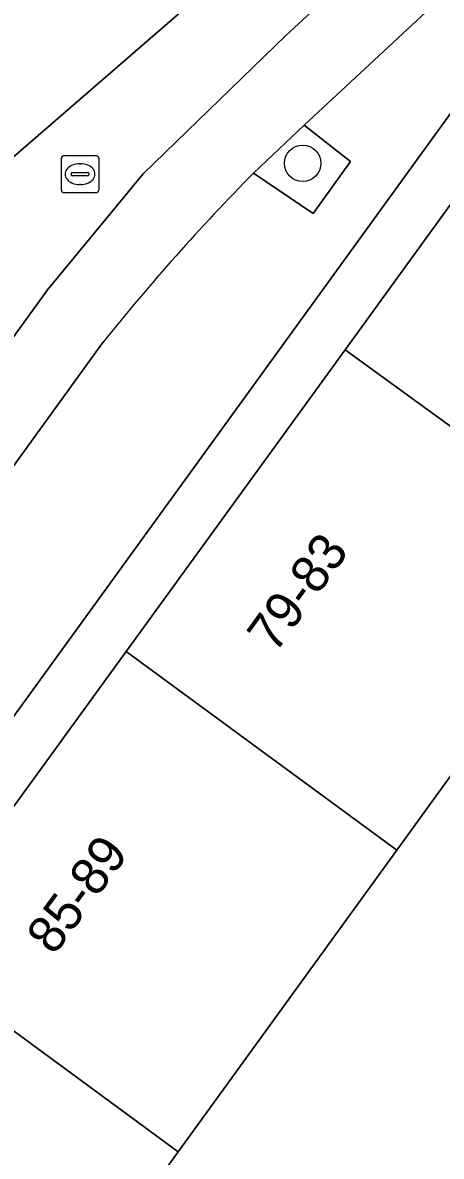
# Model space of a CAD drawing. Extents: x 160102 to 160934, y 382045 to 382923.
# Drawn here: x 160615.06 to 160626.3, y 382711.53 to 382741.96 of the extents above; entities that cross this region are included whole.
import ezdxf

# ---------------------------------------------------------------- set-up
doc = ezdxf.new("R2010")
doc.units = 0
for name, color, linetype in [('IMGEO_Berm_groen', 7, 'Continuous'), ('IMGEO_Boom', 7, 'Continuous'), ('IMGEO_Erf', 7, 'Continuous'), ('IMGEO_Fietspad_gesloten', 7, 'Continuous'), ('IMGEO_Groenvoorziening', 7, 'Continuous'), ('IMGEO_Pand', 7, 'Continuous'), ('IMGEO_Pand_nummerreeks', 7, 'Continuous'), ('IMGEO_Rijbaan_lokaal_gesloten', 7, 'Continuous'), ('IMGEO_Rioolput', 7, 'Continuous'), ('IMGEO_Voetpad_open', 7, 'Continuous')]:
    doc.layers.add(name, color=color, linetype=linetype)

msp = doc.modelspace()

# ---------------------------------------------------------------- linework, layer by layer
at = {"layer": 'IMGEO_Berm_groen'}
for points in [[(160622.116, 382741.606), (160628.941, 382747.912), (160627.337, 382749.441), (160623.499, 382745.883), (160607.777, 382732.272), (160608.096, 382731.058)], [(160611, 382728.257), (160615.726, 382734.786), (160618.296, 382737.897), (160622.116, 382741.606)]]:
    msp.add_lwpolyline(points, dxfattribs=at)
at = {"layer": 'IMGEO_Boom'}
msp.add_circle((160622.58, 382738.184), 0.489, dxfattribs=at)
at = {"layer": 'IMGEO_Erf'}
for points in [[(160627.863, 382741.339), (160608.036, 382713.994), (160608.819, 382712.639), (160609.972, 382710.65), (160610.852, 382711.865), (160612.557, 382710.607), (160614.002, 382712.583), (160610.577, 382715.045), (160610.561, 382715.057), (160611.962, 382716.987), (160617.837, 382725.08), (160623.717, 382733.179), (160629.709, 382741.434)], [(160631.007, 382727.887), (160625.108, 382719.746), (160619.24, 382711.648), (160617.366, 382709.062)]]:
    msp.add_lwpolyline(points, dxfattribs=at)
at = {"layer": 'IMGEO_Fietspad_gesloten'}
for points in [[(160680.167, 382795.521), (160667.629, 382783.858), (160655.707, 382772.815), (160651.097, 382768.481), (160646.168, 382763.905), (160634.157, 382752.637), (160628.941, 382747.912), (160622.116, 382741.606), (160618.296, 382737.897), (160615.726, 382734.786), (160611, 382728.257), (160608.445, 382724.675), (160604.005, 382718.537)], [(160621.261, 382737.92), (160622.616, 382739.208), (160657.91, 382771.975), (160669.999, 382783.221), (160681.614, 382794.046)], [(160605.653, 382717.414), (160617.215, 382733.37)]]:
    msp.add_lwpolyline(points, dxfattribs=at)
msp.add_arc((160662.873, 382696.844), 58.471, 135.37098, 141.34006, dxfattribs=at)
at = {"layer": 'IMGEO_Groenvoorziening'}
msp.add_lwpolyline([(160621.261, 382737.92), (160622.866, 382736.832), (160623.862, 382738.235), (160622.616, 382739.208)], close=True, dxfattribs=at)
at = {"layer": 'IMGEO_Pand'}
for points in [[(160631.007, 382727.887), (160636.992, 382736.147), (160633.756, 382738.496), (160629.709, 382741.434), (160623.717, 382733.179)], [(160617.837, 382725.08), (160625.108, 382719.746), (160631.007, 382727.887), (160623.717, 382733.179)], [(160617.837, 382725.08), (160611.962, 382716.987), (160619.24, 382711.648), (160625.108, 382719.746)], [(160619.24, 382711.648), (160611.962, 382716.987), (160610.561, 382715.057), (160610.577, 382715.045), (160614.002, 382712.583), (160612.557, 382710.607), (160611.201, 382708.753), (160617.769, 382702.147), (160621.532, 382705.996), (160621.42, 382706.112), (160617.366, 382709.062)]]:
    msp.add_lwpolyline(points, close=True, dxfattribs=at)
at = {"layer": 'IMGEO_Rijbaan_lokaal_gesloten'}
msp.add_lwpolyline([(160623.722, 382750.857), (160605.678, 382735.154), (160607.777, 382732.272), (160623.499, 382745.883), (160627.337, 382749.441), (160632.081, 382754.608), (160644.258, 382765.947), (160649.188, 382770.545), (160653.803, 382774.9), (160665.69, 382786.016), (160670.685, 382790.587), (160683.651, 382802.717)], dxfattribs=at)
at = {"layer": 'IMGEO_Rioolput'}
for p, q in [((160616.176, 382738.394), (160617.028, 382738.394)), ((160616.101, 382737.468), (160616.101, 382738.32)), ((160616.589, 382738.174), (160616.614, 382738.174)), ((160617.102, 382738.32), (160617.102, 382737.468)), ((160616.36, 382737.888), (160616.36, 382737.9)), ((160616.798, 382737.851), (160616.4, 382737.851)), ((160616.403, 382737.937), (160616.801, 382737.937)), ((160616.844, 382737.9), (160616.844, 382737.888)), ((160616.612, 382737.614), (160616.587, 382737.614)), ((160617.028, 382737.394), (160616.176, 382737.394))]:
    msp.add_line(p, q, dxfattribs=at)
for points in [[(160616.176, 382738.394), (160617.028, 382738.394)], [(160616.101, 382737.468), (160616.101, 382738.32)], [(160617.102, 382738.32), (160617.102, 382737.468)], [(160617.028, 382737.394), (160616.176, 382737.394)]]:
    msp.add_lwpolyline(points, dxfattribs=at)
for centre, radius, start, end in [((160616.178, 382738.318), 0.0765, 91.552, 178.448), ((160616.178, 382738.318), 0.0765, 91.552, 178.448), ((160617.026, 382738.318), 0.0765, 1.552, 88.448), ((160617.026, 382738.318), 0.0765, 1.552, 88.448), ((160616.4, 382737.897), 0.0403, 85.8775, 175.7526), ((160616.397, 382737.887), 0.0366, 178.938, 274.7102), ((160616.801, 382737.894), 0.043, 264.8664, 352.4533), ((160616.805, 382737.899), 0.0386, 1.7309, 96.639), ((160616.178, 382737.47), 0.0765, 181.552, 268.448), ((160616.178, 382737.47), 0.0765, 181.552, 268.448), ((160617.026, 382737.47), 0.0765, 271.552, 358.448), ((160617.026, 382737.47), 0.0765, 271.552, 358.448)]:
    msp.add_arc(centre, radius, start, end, dxfattribs=at)
for centre, major_axis, ratio, start_param, end_param in [((160616.588, 382737.894), (-0.387, 0.002), 0.722429, 4.712389, 7.853982), ((160616.613, 382737.894), (-0.39, 0.002), 0.717154, 1.570796, 4.712389)]:
    msp.add_ellipse(centre, major_axis=major_axis, ratio=ratio, start_param=start_param, end_param=end_param, dxfattribs=at)
at = {"layer": 'IMGEO_Voetpad_open'}
for points in [[(160681.614, 382794.046), (160669.999, 382783.221), (160657.91, 382771.975), (160622.616, 382739.208), (160623.862, 382738.235), (160622.866, 382736.832), (160621.261, 382737.92)], [(160605.334, 382714.432), (160606.999, 382711.598), (160608.819, 382712.639), (160608.036, 382713.994), (160627.863, 382741.339), (160635.89, 382749.157), (160636.803, 382750), (160640.109, 382753.053), (160644.069, 382756.709), (160648.442, 382760.747), (160648.64, 382760.93), (160652.314, 382764.338), (160653.66, 382765.577), (160655.924, 382767.662), (160656.319, 382767.295), (160659.335, 382770.161), (160659.144, 382770.644)], [(160617.215, 382733.37), (160605.653, 382717.414)]]:
    msp.add_lwpolyline(points, dxfattribs=at)
msp.add_arc((160662.873, 382696.844), 58.471, 135.37098, 141.34006, dxfattribs=at)

# ---------------------------------------------------------------- texts
at = {"layer": 'IMGEO_Pand_nummerreeks'}
for s, rotation, p in [('79-83', 54.0541, (160621.837, 382725)), ('85-89', 53.6775, (160615.903, 382716.894))]:
    msp.add_text(s, height=1, rotation=rotation, dxfattribs=at).set_placement(p)

doc.saveas('drawing.dxf')
